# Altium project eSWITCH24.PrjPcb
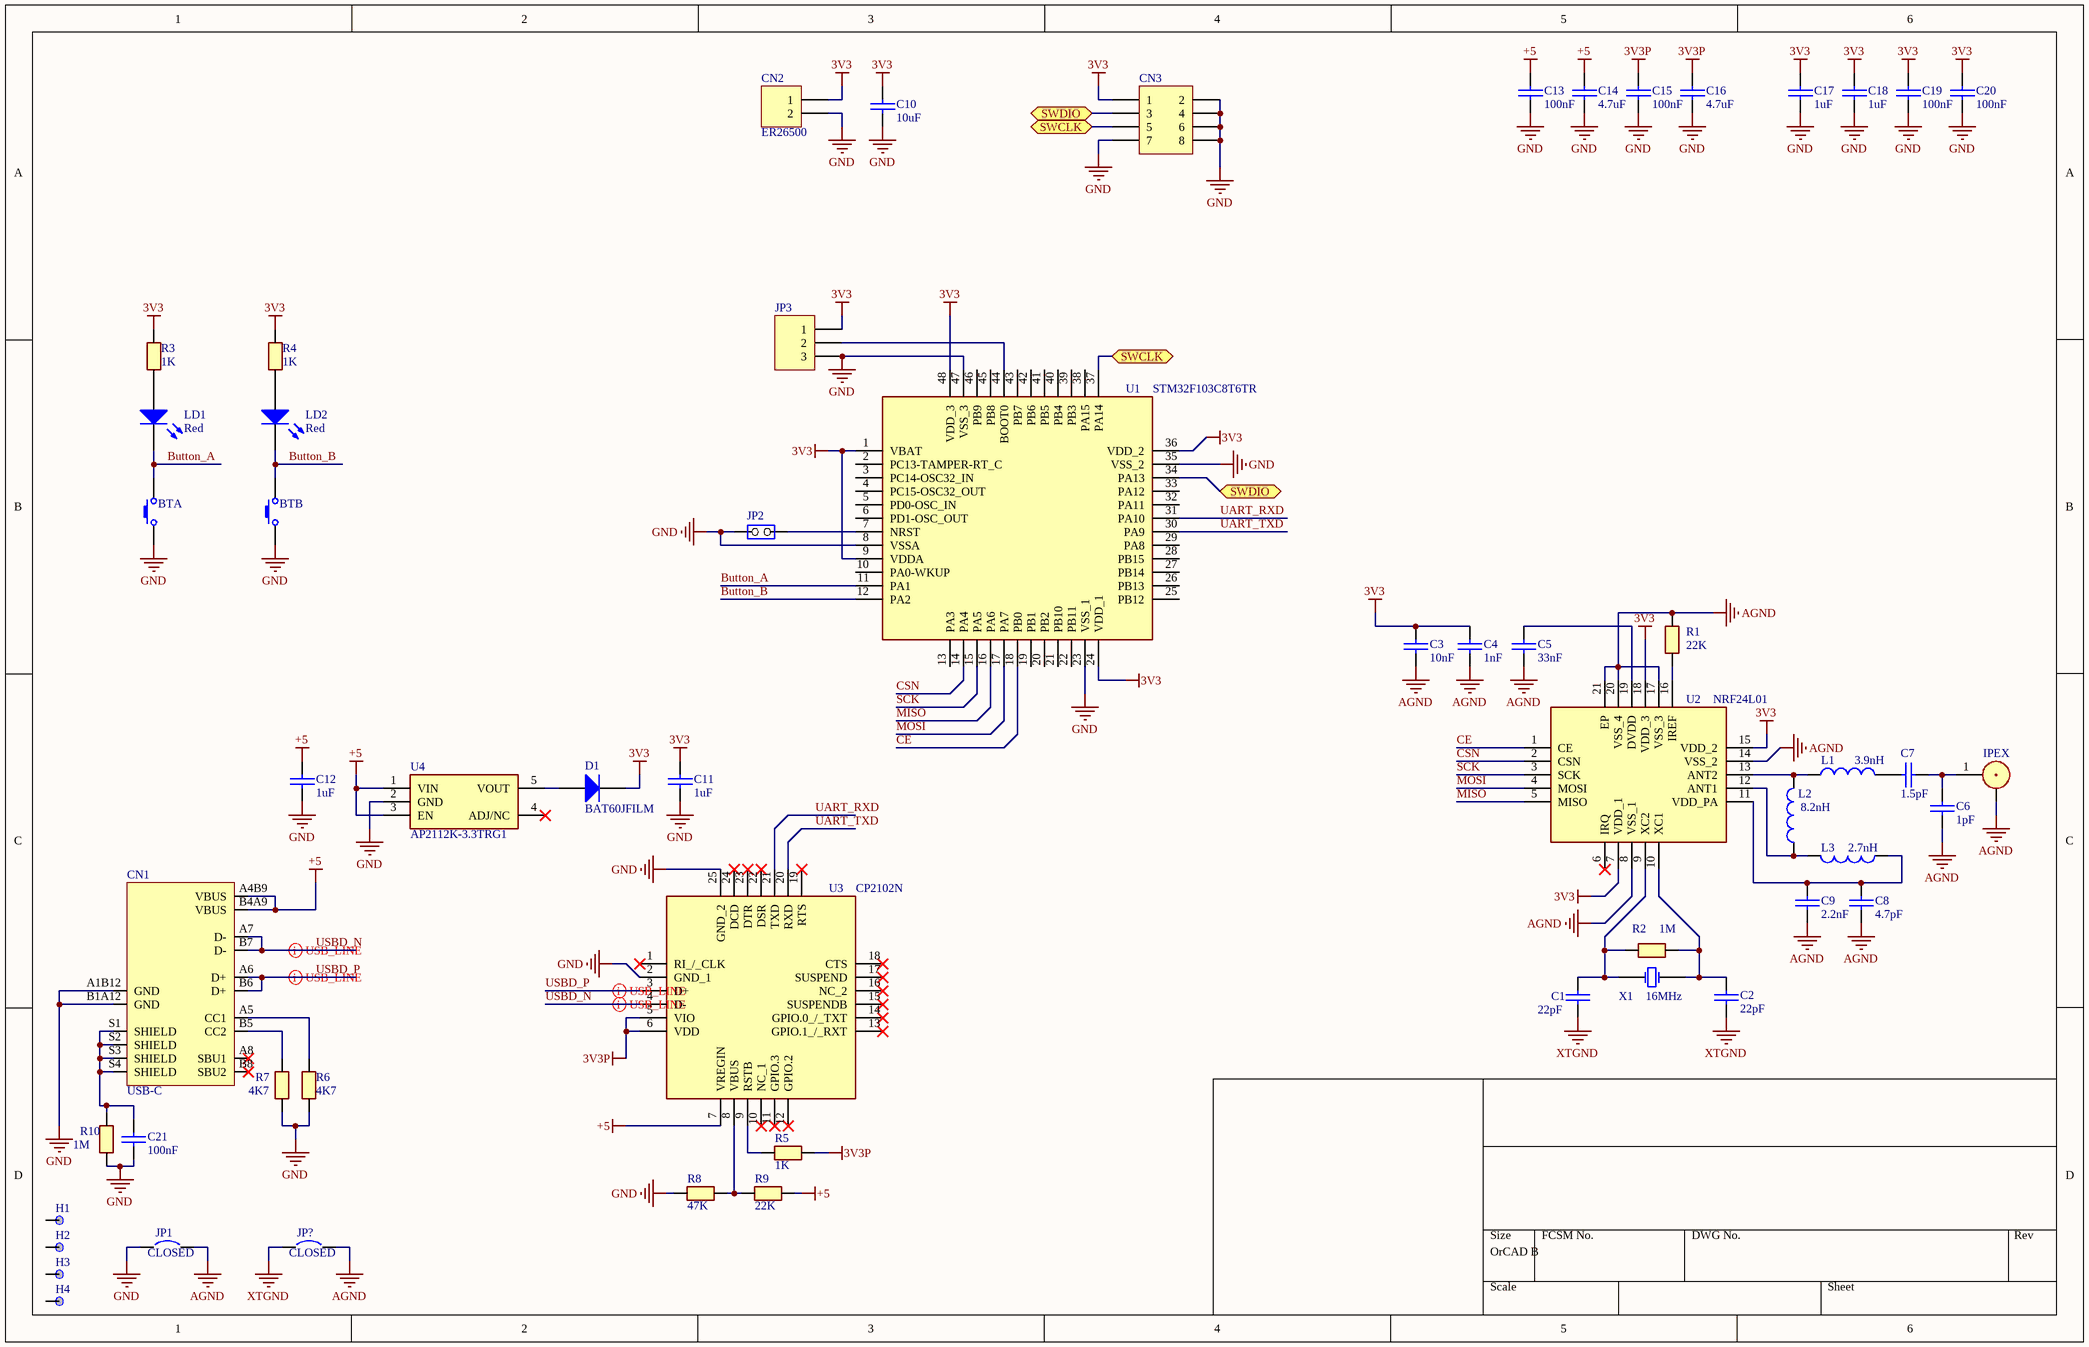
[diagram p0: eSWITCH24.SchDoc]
1 sheet, 56 parts. Net scope: flat (ports and power ports of the same name join across sheets).
Board file: PCB-eSWITCH.PcbDoc

## Sheet eSWITCH24.SchDoc
size OrCAD B; SheetNumber: 1; SheetTotal: 1

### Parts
BTA  SWITCH  [SKPMAME010]  (value not drawn)
BTB  SWITCH  [SKPMAME010]  (value not drawn)
C1  22pF  [0603C]
C2  22pF  [0603C]
C3  10nF  [0603C]
C4  1nF  [0603C]
C5  33nF  [0603C]
C6  1pF  [0603C]
C7  1.5pF  [0603C]
C8  4.7pF  [0603C]
C9  2.2nF  [0603C]
C10  10uF  [CAPC2012X94N]
C11  1uF  [CAPC2012X94N]
C12  1uF  [CAPC2012X94N]
C13  100nF  [CAPC2012X94N]
C14  4.7uF  [CAPC2012X94N]
C15  100nF  [CAPC2012X94N]
C16  4.7uF  [CAPC2012X94N]
C17  1uF  [CAPC2012X94N]
C18  1uF  [CAPC2012X94N]
C19  100nF  [0603C]
C20  100nF  [0603C]
C21  100nF  [CAPC2012X94N]
CN1  USB-C  [USB TYPE C]
CN2  ER26500  [HDR1X2]
CN3  JTAG/SWD  [MINI PIN HEADER 2X4]  (value not drawn)
D1  BAT60JFILM  [SOD-323]
H1  (no value)  [MOUNTING HOLE]
H2  (no value)  [MOUNTING HOLE]
H3  (no value)  [MOUNTING HOLE]
H4  (no value)  [MOUNTING HOLE]
IPEX  SMA  [IPEX]  (value not drawn)
JP1  CLOSED  [SB_0603]
JP2  JP2  [HDR_1x2_2R54_V_M_S]  (value not drawn)
JP3  Header 3  [HDR1X3]  (value not drawn)
JP?  CLOSED  [SB_0603]
L1  3.9nH  [RESC1608X55N]
L2  8.2nH  [RESC1608X55N]
L3  2.7nH  [RESC1608X55N]
LD1  Red  [0603D-R]
LD2  Red  [0603D-R]
R1  22K  [0603R]
R2  1M  [0603R]
R3  1K  [0603R]
R4  1K  [0603R]
R5  1K  [0603R]
R6  4K7  [0603R]
R7  4K7  [0603R]
R8  47K  [0603R]
R9  22K  [0603R]
R10  1M  [0603R]
U1  STM32F103C8T6TR  [QFP50P900X900X160-48N]
U2  NRF24L01  [QFN50P400X400X95-21N-D]
U3  CP2102N  [QFN50P400X400X80-25N-D]
U4  AP2112K-3.3TRG1  [SOT95P282X130-5N]
X1  16MHz  [XTAL_SMD]

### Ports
SWCLK (bidir), SWDIO (bidir)

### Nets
3V3: C3.1 C4.1 C10.1 C11.1 C17.1 C18.1 C19.2 C20.2 CN2.1 CN3.1 D1.2(K) JP3.1 R3.2 R4.2 U1.1(VBAT) U1.9(VDDA) U1.24(VDD_1) U1.36(VDD_2) U1.48(VDD_3) U2.7(VDD_1) U2.15(VDD_2) U2.18(VDD_3)
3V3P: C15.1 C16.1 R5.1 U3.5(VIO) U3.6(VDD)
+5: C12.1 C13.1 C14.1 CN1.A4B9(VBUS) CN1.B4A9(VBUS) R9.1 U3.7(VREGIN) U4.1(VIN) U4.3(EN)
AGND: C3.2 C4.2 C5.2 C6.2 C8.1 C9.1 IPEX.2 JP1.2 JP?.2 R1.2 U2.8(VSS_1) U2.14(VSS_2) U2.17(VSS_3) U2.20(VSS_4) U2.21(EP)
GND: BTA.1 BTB.1 C10.2 C11.2 C12.2 C13.2 C14.2 C15.2 C16.2 C17.2 C18.2 C19.1 C20.1 C21.2 CN1.A1B12(GND) CN1.B1A12(GND) CN2.2 CN3.2 CN3.4 CN3.6 CN3.7 CN3.8 JP1.1 JP2.1(COMMON) JP3.3 R6.1 R7.1 R8.2 R10.1 U1.8(VSSA) U1.23(VSS_1) U1.35(VSS_2) U1.47(VSS_3) U3.2(GND_1) U3.25(GND_2) U4.2(GND)
XTGND: C1.2 C2.2 JP?.1
Button_A: BTA.2 LD1.2(K) U1.11(PA1)
Button_B: BTB.2 LD2.2(K) U1.12(PA2)
CE: U1.18(PB0) U2.1(CE)
CSN: U1.14(PA4) U2.2(CSN)
MISO: U1.16(PA6) U2.5(MISO)
MOSI: U1.17(PA7) U2.4(MOSI)
SCK: U1.15(PA5) U2.3(SCK)
UART_RXD: U1.31(PA10) U3.21(TXD)
UART_TXD: U1.30(PA9) U3.20(RXD)
USBD_N: CN1.A7(D-) CN1.B7(D-) U3.4(D-)
USBD_P: CN1.A6(D+) CN1.B6(D+) U3.3(D+)
NetC1_1: C1.1 R2.2 U2.9(XC2) X1.1(OSC1)
NetC2_1: C2.1 R2.1 U2.10(XC1) X1.3(OSC2)
NetC5_1: C5.1 U2.19(DVDD)
NetC6_1: C6.1 C7.2 IPEX.1
NetC7_1: C7.1 L1.2
NetC8_2: C8.2 C9.2 L3.1 U2.11(VDD_PA)
NetC21_1: C21.1 CN1.S1(SHIELD) CN1.S2(SHIELD) CN1.S3(SHIELD) CN1.S4(SHIELD) R10.2
NetCN1_A5: CN1.A5(CC1) R6.2
NetCN1_B5: CN1.B5(CC2) R7.2
NetCN3_3: CN3.3 U1.34(PA13) ; port SWDIO
NetCN3_5: CN3.5 U1.37(PA14) ; port SWCLK
NetD1_1: D1.1(A) U4.5(VOUT)
NetJP2_2: JP2.2(NO) U1.7(NRST)
NetJP3_2: JP3.2 U1.44(BOOT0)
NetL1_1: L1.1 L2.2 U2.13(ANT2)
NetL2_1: L2.1 L3.2 U2.12(ANT1)
NetLD1_1: LD1.1(A) R3.1
NetLD2_1: LD2.1(A) R4.1
NetR1_1: R1.1 U2.16(IREF)
NetR5_2: R5.2 U3.9(RSTB)
NetR8_1: R8.1 R9.2 U3.8(VBUS)

Not connected (* = marked no-connect by the designer): CN1 A8(SBU1)* B8(SBU2)*; H1 1; H2 1; H3 1; H4 1; U1 2(PC13-TAMPER-RT_C) 3(PC14-OSC32_IN) 4(PC15-OSC32_OUT) 5(PD0-OSC_IN) 6(PD1-OSC_OUT) 10(PA0-WKUP) 13(PA3) 19(PB1) 20(PB2) 21(PB10) 22(PB11) 25(PB12) 26(PB13) 27(PB14) 28(PB15) 29(PA8) 32(PA11) 33(PA12) 38(PA15) 39(PB3) 40(PB4) 41(PB5) 42(PB6) 43(PB7) 45(PB8) 46(PB9); U2 6(IRQ)*; U3 1(RI_/_CLK)* 10(NC_1)* 11(GPIO.3)* 12(GPIO.2)* 13(GPIO.1_/_RXT)* 14(GPIO.0_/_TXT)* 15(SUSPENDB)* 16(NC_2)* 17(SUSPEND)* 18(CTS)* 19(RTS)* 22(DSR)* 23(DTR)* 24(DCD)*; U4 4(ADJ/NC)*

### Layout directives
differential pair: USBD_N, USBD_P

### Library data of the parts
C1-C21 = CAP: Capacitor
CN2 = Header 2: Header, 2-Pin
CN3 = Header 4X2: Header, 4-Pin, Dual row
D1 = BAT60JFILM: Manuf_1: STM; Provided: ST; ECCN_US/EU: EAR99/NEC
H1-H4 = TP
IPEX = SMA: pin to pad: 1>3 2>1+2
JP1 JP? = Circuit Breaker
JP3 = Header 3: Header, 3-Pin
L1-L3 = Inductor: Code_IEC: 1005; Value: 10mH
LD1 LD2 = LED2: Typical RED, GREEN, YELLOW, AMBER GaAs LED
R1-R10 = RESISTOR
U1 = STM32F103C8T6TR: Integrated Circuit; Manufacturer_Name: STMicroelectronics
U2 = NRF24L01: Integrated Circuit; Manufacturer_Name: Nordic Semiconductor; Description: RF Transceiver 1.9-3.6V 2.4GHz XCVR ENHNCD SHCKBRST
U4 = AP2112K-3.3TRG1: Integrated Circuit; Manufacturer_Name: Diodes Inc.
X1 = XTAL_5032: Crystal Oscillator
